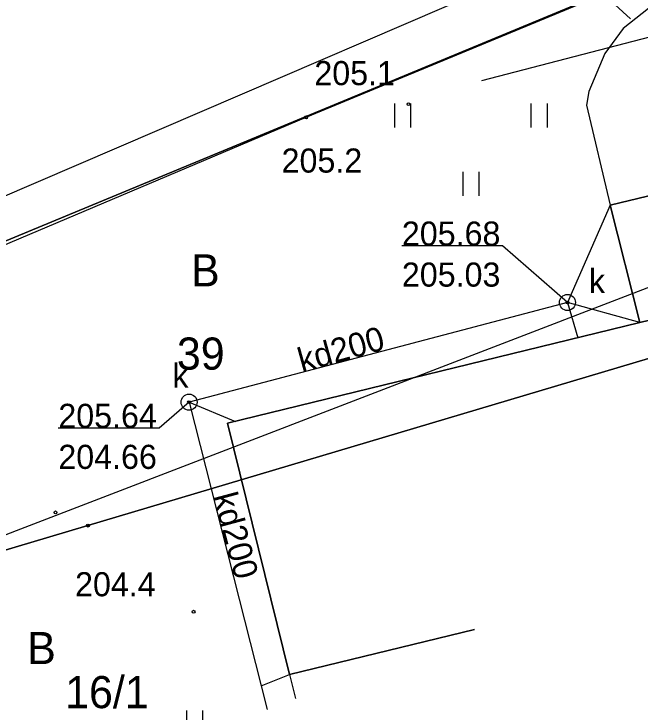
# Model space of a CAD drawing. Extents: x 6512400 to 6513200, y 6022500 to 6022750.
# Drawn here: x 6512825.93 to 6512845.42, y 6022556.82 to 6022578.54 of the extents above; entities that cross this region are included whole.
import ezdxf

# ---------------------------------------------------------------- set-up
doc = ezdxf.new("R2010")
doc.units = 0
for name, color, linetype in [('203-punkt graniczny', 7, 'Continuous'), ('210-oznaczenie konturu użytku gruntowego', 7, 'Continuous'), ('211-numer działki ewidencyjnej', 7, 'Continuous'), ('216-obręb ewidencyjny', 7, 'Continuous'), ('217-kontur klasyfikacyjny', 7, 'Continuous'), ('218-kontur użytku gruntowego', 7, 'Continuous'), ('219-działka ewidencyjna', 7, 'Continuous'), ('312-budynek ewidencyjny', 7, 'Continuous'), ('320-blok - kondygnacja nadziemna', 7, 'Continuous'), ('940-Trawnik symb.', 7, 'Continuous'), ('940-Trawnik symb. poj.', 7, 'Continuous'), ('chodnik (powierzchnia)', 7, 'Continuous'), ('jezdnia (powierzchnia)', 7, 'Continuous'), ('Obszar opracowania', 7, 'Continuous'), ('ogrodzenie trwałe', 7, 'Continuous'), ('pikieta naturalna', 7, 'Continuous'), ('pikieta naturalna-Atr2', 7, 'Continuous'), ('przewód kanalizacyjny (linia)', 7, 'Continuous'), ('przewód kanalizacyjny (linia)-Atr1', 7, 'Continuous'), ('punkt o określonej wysokości (sieć kanalizacyjna)', 7, 'Continuous'), ('punkt o określonej wysokości (sieć kanalizacyjna)-Atr2', 7, 'Continuous'), ('punkt o określonej wysokości (sieć kanalizacyjna)-Atr3', 7, 'Continuous'), ('punkt wysokościowy naturalny', 7, 'Continuous'), ('punkt wysokościowy naturalny-Atr2', 7, 'Continuous'), ('urządzenie techniczne projektowane lub w budowie (sieć kanalizacyjna) - powierzchnia - ob. projektowany', 7, 'Continuous'), ('właz okrągły - siec kanalizacyjna (punkt)', 7, 'Continuous'), ('właz okrągły - siec kanalizacyjna (punkt)-Atr17', 7, 'Continuous')]:
    doc.layers.add(name, color=color, linetype=linetype)

# ---------------------------------------------------------------- blocks, each defined once
blk = doc.blocks.new('203')
blk.add_circle((0, 0), 0.045)
blk = doc.blocks.new('PW01')
blk.add_circle((0, 0), 0.045)
blk = doc.blocks.new('US22')
blk.add_circle((0, 0), 0.25)
blk = doc.blocks.new('940')
for p, q in [((-2.374, 1.749), (-2.374, 2.499)), ((-1.874, 1.749), (-1.874, 2.499)), ((1.874, 1.749), (1.874, 2.499)), ((2.374, 1.749), (2.374, 2.499)), ((-0.25, -0.375), (-0.25, 0.375)), ((0.25, -0.375), (0.25, 0.375))]:
    blk.add_line(p, q)
blk = doc.blocks.new('940P')
for p, q in [((-0.25, -0.375), (-0.25, 0.375)), ((0.25, -0.375), (0.25, 0.375))]:
    blk.add_line(p, q)

msp = doc.modelspace()

# ---------------------------------------------------------------- linework, layer by layer
at = {"layer": '216-obręb ewidencyjny'}
for points in [[(6512836.687, 6022675.173), (6512833.61, 6022675.02), (6512828.67, 6022670.98), (6512801.96, 6022670.34), (6512810.18, 6022663.28), (6512825.37, 6022649.66), (6512838.47, 6022634.29), (6512852.25, 6022608.25), (6512853.17, 6022604.51), (6512855.78, 6022583.95), (6512858.85, 6022571.74), (6512828.23, 6022562.62), (6512818.47, 6022559.72), (6512824.714, 6022553.406)], [(6512780.7, 6022581.02), (6512806.2, 6022572.11), (6512806.62, 6022563.51), (6512811.41, 6022558.95), (6512818.47, 6022559.72), (6512828.23, 6022562.62), (6512858.85, 6022571.74), (6512855.78, 6022583.95), (6512853.17, 6022604.51), (6512852.25, 6022608.25), (6512838.47, 6022634.29), (6512825.37, 6022649.66), (6512810.18, 6022663.28), (6512801.96, 6022670.34), (6512796.96, 6022674.74), (6512790.49, 6022674.74), (6512785.56, 6022674.74), (6512768.24, 6022674.27)]]:
    msp.add_lwpolyline(points, dxfattribs=at)
at = {"layer": '217-kontur klasyfikacyjny'}
msp.add_lwpolyline([(6512825.22, 6022571.29), (6512855.78, 6022583.95)], dxfattribs=at)
at = {"layer": '218-kontur użytku gruntowego'}
for points in [[(6512825.22, 6022571.29), (6512855.78, 6022583.95)], [(6512855.78, 6022583.95), (6512825.22, 6022571.29)], [(6512858.85, 6022571.74), (6512828.23, 6022562.62)], [(6512828.23, 6022562.62), (6512858.85, 6022571.74)], [(6512828.23, 6022562.62), (6512818.47, 6022559.72)], [(6512818.47, 6022559.72), (6512828.23, 6022562.62)]]:
    msp.add_lwpolyline(points, dxfattribs=at)
at = {"layer": '219-działka ewidencyjna'}
for points in [[(6512825.22, 6022571.29), (6512855.78, 6022583.95)], [(6512858.85, 6022571.74), (6512828.23, 6022562.62)], [(6512828.23, 6022562.62), (6512818.47, 6022559.72)]]:
    msp.add_lwpolyline(points, dxfattribs=at)
at = {"layer": '312-budynek ewidencyjny'}
for points in [[(6512844.49, 6022572.59), (6512851.42, 6022574.26)], [(6512845.41, 6022568.94), (6512844.49, 6022572.59)], [(6512832.58, 6022565.81), (6512845.41, 6022568.94)], [(6512834.51, 6022557.99), (6512832.58, 6022565.81)], [(6512840.268, 6022559.387), (6512834.51, 6022557.99)]]:
    msp.add_lwpolyline(points, dxfattribs=at)
at = {"layer": '320-blok - kondygnacja nadziemna'}
msp.add_lwpolyline([(6512845.41, 6022568.94), (6512852.38, 6022570.62), (6512851.42, 6022574.26), (6512844.49, 6022572.59)], close=True, dxfattribs=at)
msp.add_lwpolyline([(6512858.916, 6022566.557), (6512857.62, 6022571.91), (6512852.38, 6022570.62), (6512845.41, 6022568.94), (6512832.58, 6022565.81), (6512834.51, 6022557.99), (6512840.268, 6022559.387)], dxfattribs=at)
at = {"layer": 'chodnik (powierzchnia)'}
msp.add_lwpolyline([(6512840.268, 6022559.387), (6512834.51, 6022557.99), (6512834.693, 6022557.243)], dxfattribs=at)
at = {"layer": 'jezdnia (powierzchnia)'}
msp.add_lwpolyline([(6512857.37, 6022576.01), (6512857.16, 6022576.8), (6512855.73, 6022582.41), (6512855.52, 6022583.23), (6512847.9, 6022580.14), (6512846.52, 6022579.38), (6512844.89, 6022578.08), (6512844.32, 6022577.3), (6512843.83, 6022576.12), (6512843.75, 6022575.7), (6512844.49, 6022572.59), (6512851.42, 6022574.26), (6512851.6, 6022573.59), (6512851.75, 6022573.46), (6512852.45, 6022574.3), (6512853.58, 6022574.86), (6512856.56, 6022575.84)], close=True, dxfattribs=at)
at = {"layer": 'Obszar opracowania'}
msp.add_lwpolyline([(6512710.98, 6022693.84), (6512748.35, 6022694.16), (6512798.11, 6022695.25), (6512807.47, 6022695.46), (6512809.66, 6022606.87), (6512863.71, 6022622.03), (6512875.13, 6022581.36), (6512755.22, 6022535.25), (6512691.61, 6022568.03), (6512709.16, 6022605.16)], close=True, dxfattribs=at)
at = {"layer": 'ogrodzenie trwałe'}
msp.add_lwpolyline([(6512818.46, 6022560.27), (6512812.53, 6022565.9), (6512821.8, 6022569.74), (6512835.02, 6022575.32), (6512844.28, 6022579.16), (6512845.12, 6022578.38)], dxfattribs=at)
at = {"layer": 'przewód kanalizacyjny (linia)'}
for points in [[(6512840.49, 6022576.47), (6512866.73, 6022583.29)], [(6512844.49, 6022572.59), (6512843.16, 6022569.56)], [(6512843.16, 6022569.56), (6512831.38, 6022566.46)], [(6512843.16, 6022569.56), (6512843.48, 6022568.46)], [(6512845.41, 6022568.94), (6512843.16, 6022569.56)], [(6512831.38, 6022566.46), (6512832.82, 6022565.86)], [(6512831.38, 6022566.46), (6512833.62, 6022557.64), (6512833.806, 6022556.902)], [(6512833.62, 6022557.64), (6512834.51, 6022557.99)]]:
    msp.add_lwpolyline(points, dxfattribs=at)
at = {"layer": 'punkt o określonej wysokości (sieć kanalizacyjna)-Atr2'}
for points in [[(6512843.16, 6022569.56), (6512841.14, 6022571.32), (6512838.005, 6022571.32)], [(6512831.38, 6022566.46), (6512830.45, 6022565.65), (6512827.309, 6022565.65)]]:
    msp.add_lwpolyline(points, dxfattribs=at)
at = {"layer": 'urządzenie techniczne projektowane lub w budowie (sieć kanalizacyjna) - powierzchnia - ob. projektowany'}
msp.add_lwpolyline([(6512852.09, 6022584.23), (6512820.25, 6022570.56)], dxfattribs=at)

# ---------------------------------------------------------------- block references
at = {"layer": '203-punkt graniczny'}
msp.add_blockref('203', (6512828.23, 6022562.62), dxfattribs=at)
at = {"layer": '940-Trawnik symb.'}
msp.add_blockref('940', (6512840.16, 6022573.25), dxfattribs=at)
at = {"layer": '940-Trawnik symb. poj.'}
msp.add_blockref('940P', (6512831.56, 6022556.49), dxfattribs=at)
at = {"layer": 'pikieta naturalna'}
msp.add_blockref('PW01', (6512835.02, 6022575.32), dxfattribs=at)
at = {"layer": 'punkt o określonej wysokości (sieć kanalizacyjna)'}
for p in [(6512843.16, 6022569.56), (6512831.38, 6022566.46)]:
    msp.add_blockref('PW01', p, dxfattribs=at)
at = {"layer": 'punkt wysokościowy naturalny'}
for p in [(6512838.21, 6022575.73), (6512827.22, 6022563.03), (6512831.52, 6022559.94)]:
    msp.add_blockref('PW01', p, dxfattribs=at)
at = {"layer": 'właz okrągły - siec kanalizacyjna (punkt)'}
for p in [(6512843.16, 6022569.56), (6512831.38, 6022566.46)]:
    msp.add_blockref('US22', p, dxfattribs=at)

# ---------------------------------------------------------------- texts
at = {"layer": '210-oznaczenie konturu użytku gruntowego'}
for p in [(6512831.44, 6022570.06), (6512826.34, 6022558.31)]:
    msp.add_text('B', height=1, dxfattribs=at).set_placement(p)
at = {"layer": '211-numer działki ewidencyjnej'}
for s, p in [('39', (6512831, 6022567.47)), ('16/1', (6512827.52, 6022556.94))]:
    msp.add_text(s, height=1, dxfattribs=at).set_placement(p)
at = {"layer": 'pikieta naturalna-Atr2'}
msp.add_text('205.2', height=0.75, dxfattribs=at).set_placement((6512834.26, 6022573.6))
at = {"layer": 'przewód kanalizacyjny (linia)-Atr1'}
for rotation, p in [(15.519, (6512834.89, 6022567.38)), (285.028, (6512832.12, 6022563.54))]:
    msp.add_text('kd200', height=0.75, rotation=rotation, dxfattribs=at).set_placement(p)
at = {"layer": 'punkt o określonej wysokości (sieć kanalizacyjna)-Atr2'}
for s, p in [('205.68', (6512838.005, 6022571.328)), ('205.64', (6512827.309, 6022565.658))]:
    msp.add_text(s, height=0.75, dxfattribs=at).set_placement(p)
at = {"layer": 'punkt o określonej wysokości (sieć kanalizacyjna)-Atr3'}
for s, p in [('205.03', (6512838.005, 6022570.053)), ('204.66', (6512827.309, 6022564.383))]:
    msp.add_text(s, height=0.75, dxfattribs=at).set_placement(p)
at = {"layer": 'punkt wysokościowy naturalny-Atr2'}
for s, p in [('205.1', (6512835.28, 6022576.32)), ('204.4', (6512827.83, 6022560.42))]:
    msp.add_text(s, height=0.75, dxfattribs=at).set_placement(p)
at = {"layer": 'właz okrągły - siec kanalizacyjna (punkt)-Atr17'}
for p in [(6512843.83, 6022569.85), (6512830.86, 6022566.91)]:
    msp.add_text('k', height=0.75, dxfattribs=at).set_placement(p)

doc.saveas('drawing.dxf')
